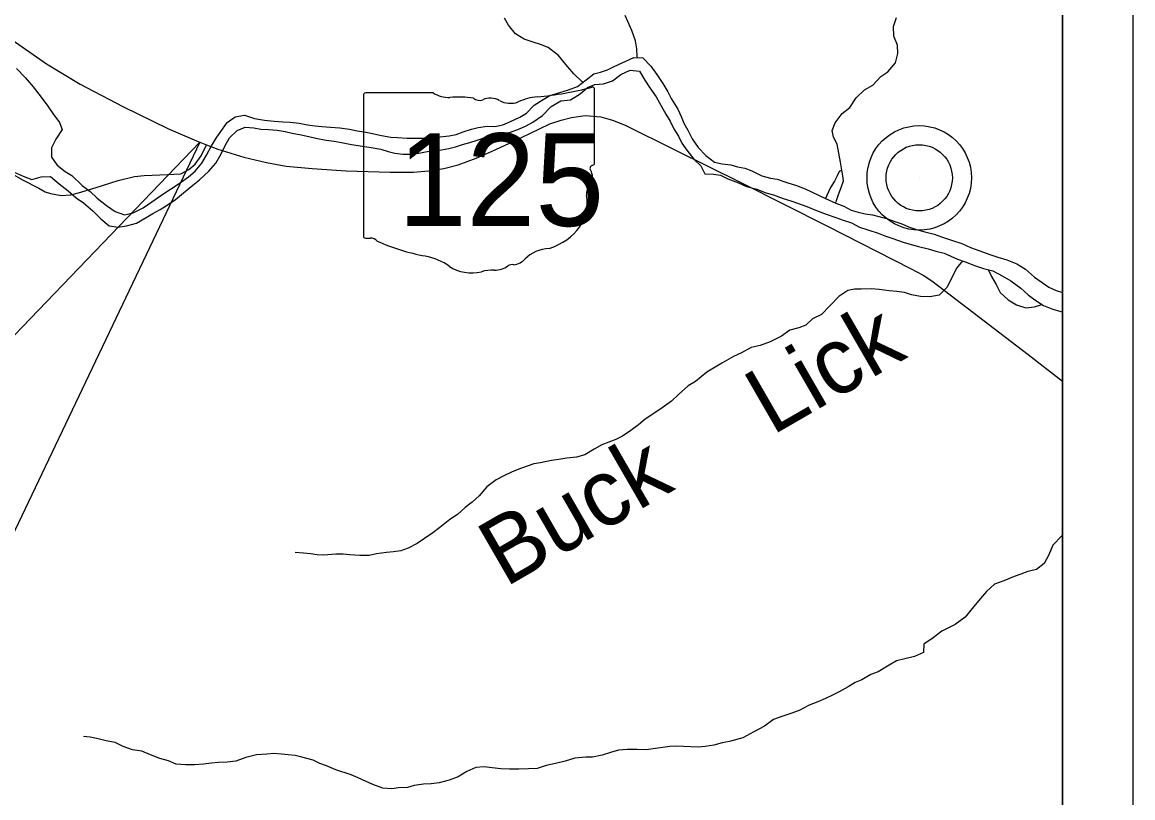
# Model space of a CAD drawing. Extents: x 0 to 34, y 0 to 22.
# Drawn here: x 7.417 to 9, y 15.178 to 16.283 of the extents above; entities that cross this region are included whole.
import ezdxf

# ---------------------------------------------------------------- set-up
doc = ezdxf.new("R2010")
doc.units = 0
for name, color, linetype in [('Default', 7, 'Continuous'), ('GM_X_Major_River', 7, 'Continuous'), ('GM_X_Minor_Lake', 7, 'Continuous'), ('GM_X_Minor_River', 7, 'Continuous'), ('GM_X_Minor_River_Text', 7, 'Continuous'), ('GM_X_State_Location', 7, 'Continuous'), ('GM_X_State_Route', 7, 'Continuous'), ('GM_X_State_Shield', 7, 'Continuous'), ('GM_X_Township_Road', 7, 'Continuous'), ('GM_X_Unincorporated', 7, 'Continuous'), ('GM_X_Unincorporated_Location', 7, 'Continuous'), ('SH_Cut_Line', 7, 'Continuous'), ('SH_Data', 7, 'Continuous'), ('SH_Text', 7, 'Continuous')]:
    doc.layers.add(name, color=color, linetype=linetype)

msp = doc.modelspace()

# ---------------------------------------------------------------- linework, layer by layer
at = {"layer": 'Default'}
msp.add_lwpolyline([(8.9, 14.1), (8.9, 18.9397), (8.8678, 19.0216), (8.806, 19.0402), (8.8461, 19.2253)], dxfattribs=at)
at = {"layer": 'GM_X_Major_River'}
msp.add_line((8.5619, 16.0315), (8.5766, 16.0251), dxfattribs=at)
for points in [[(7.4671, 16.0794), (7.4782, 16.07), (7.4877, 16.0643), (7.5025, 16.0503), (7.514, 16.0415), (7.5239, 16.0321), (7.5372, 16.0218), (7.5498, 16.0131), (7.5627, 16.0086), (7.5753, 16.0113), (7.5893, 16.0185), (7.6019, 16.0269), (7.6148, 16.0361), (7.6285, 16.0452), (7.6407, 16.0532), (7.654, 16.0627), (7.6635, 16.0707), (7.6729, 16.0818), (7.6798, 16.0936), (7.687, 16.1069), (7.6946, 16.1191), (7.7025, 16.1305), (7.709, 16.14), (7.7208, 16.148), (7.7341, 16.1503), (7.7482, 16.1458), (7.7623, 16.1435), (7.776, 16.142), (7.7885, 16.1409), (7.7988, 16.1406), (7.8117, 16.1391), (7.8239, 16.1368), (7.8346, 16.135), (7.8441, 16.1342), (7.8563, 16.1335), (7.87, 16.1324), (7.8837, 16.1305), (7.8947, 16.1282), (7.9046, 16.1267), (7.9141, 16.1249), (7.9293, 16.1215), (7.9427, 16.1192), (7.9522, 16.1185), (7.9659, 16.1178), (7.9758, 16.1178), (7.9883, 16.1178), (8.0016, 16.1178), (8.0127, 16.1194), (8.0256, 16.1209), (8.0355, 16.1229), (8.0457, 16.1267), (8.0575, 16.1305), (8.067, 16.1328), (8.08, 16.1347), (8.0906, 16.1344), (8.102, 16.1367), (8.1119, 16.1409), (8.1264, 16.1477), (8.1359, 16.1531), (8.1469, 16.1645), (8.1594, 16.1725), (8.1689, 16.1786), (8.1834, 16.1828), (8.1956, 16.1866), (8.2085, 16.1912), (8.2207, 16.2008), (8.2317, 16.2091), (8.2412, 16.2118), (8.2511, 16.2149), (8.2606, 16.2195), (8.2887, 16.2324)], [(8.2887, 16.2324), (8.3016, 16.2321), (8.3131, 16.2203), (8.3218, 16.2082), (8.3302, 16.1953), (8.3371, 16.1835), (8.3421, 16.174), (8.3516, 16.1589), (8.3562, 16.1486), (8.36, 16.1391), (8.3657, 16.1289), (8.3718, 16.1167), (8.3806, 16.1042), (8.3913, 16.0929), (8.4038, 16.0834), (8.4149, 16.0811), (8.4271, 16.0796), (8.4366, 16.077), (8.4469, 16.0747), (8.4568, 16.071), (8.4712, 16.0638), (8.4834, 16.0608), (8.4929, 16.0593), (8.507, 16.0547), (8.5207, 16.0502), (8.5329, 16.0453), (8.5619, 16.0315)], [(7.9705, 16.095), (7.9823, 16.0961), (7.9918, 16.0981), (8.0032, 16.1), (8.0146, 16.1011), (8.0252, 16.1031), (8.0347, 16.1054), (8.0446, 16.1084), (8.0549, 16.1115), (8.0656, 16.1149), (8.0766, 16.1188), (8.088, 16.1211), (8.1009, 16.1238), (8.1131, 16.1261), (8.126, 16.131), (8.1355, 16.1352), (8.145, 16.1406), (8.1587, 16.1501), (8.1712, 16.1627), (8.1846, 16.171), (8.1986, 16.1722), (8.2123, 16.181), (8.2229, 16.1897), (8.2332, 16.1939), (8.2458, 16.1951), (8.2583, 16.1993), (8.2705, 16.2081), (8.2838, 16.2146), (8.2971, 16.2131), (8.3047, 16.2002), (8.3116, 16.1892), (8.3208, 16.1763), (8.3276, 16.1638), (8.3345, 16.152), (8.3406, 16.1418), (8.3459, 16.1307), (8.3524, 16.1205), (8.3574, 16.1103), (8.3646, 16.1004), (8.3745, 16.0875), (8.3841, 16.078), (8.3898, 16.0666), (8.4024, 16.0663), (8.4122, 16.0648), (8.4229, 16.0595), (8.4378, 16.0538), (8.4496, 16.0489), (8.464, 16.0448), (8.477, 16.0399), (8.488, 16.0368), (8.5017, 16.0319), (8.5124, 16.0285), (8.5223, 16.0251), (8.5352, 16.0202), (8.5493, 16.0146), (8.563, 16.0093), (8.5767, 16.0047), (8.5874, 16.001), (8.5992, 15.9968), (8.6106, 15.9907), (8.6224, 15.987), (8.6369, 15.9821), (8.6468, 15.9783), (8.6578, 15.9749), (8.6726, 15.9696), (8.6841, 15.9662), (8.6947, 15.9632), (8.7084, 15.9598), (8.7195, 15.9568), (8.7313, 15.9538), (8.7408, 15.9496), (8.7503, 15.9451), (8.7613, 15.9413), (8.7758, 15.936), (8.7872, 15.9322), (8.8006, 15.9289), (8.8139, 15.9217), (8.8264, 15.9145), (8.8405, 15.9039), (8.8508, 15.8944), (8.8604, 15.8872), (8.8725, 15.8792), (8.8847, 15.8743), (8.8973, 15.8709), (8.9, 15.8702)], [(7.4576, 16.0631), (7.4698, 16.0525), (7.4824, 16.0426), (7.4938, 16.0328), (7.5045, 16.0256), (7.5178, 16.0142), (7.5293, 16.0028), (7.5411, 15.9926), (7.554, 15.9907), (7.5658, 15.9926), (7.5802, 15.9965), (7.5939, 16.0045), (7.6034, 16.0102), (7.6137, 16.0159), (7.6236, 16.022), (7.6357, 16.0304), (7.6468, 16.0396), (7.6601, 16.0506), (7.6699, 16.0582), (7.6829, 16.0704), (7.6931, 16.0822), (7.7003, 16.0944), (7.706, 16.1062), (7.7125, 16.1183), (7.7235, 16.1286), (7.7349, 16.1332), (7.7474, 16.1325), (7.757, 16.1306), (7.768, 16.1299), (7.7806, 16.1288), (7.792, 16.1269), (7.8019, 16.1246), (7.8148, 16.1224), (7.8258, 16.1201), (7.8357, 16.1175), (7.8502, 16.1148), (7.8616, 16.1134), (7.8723, 16.1115), (7.8864, 16.1088), (7.9023, 16.1062), (7.9145, 16.1044), (7.9282, 16.1021), (7.9389, 16.0987), (7.9484, 16.0964), (7.9598, 16.095), (7.9705, 16.095)], [(8.5766, 16.0251), (8.5776, 16.0289), (8.5807, 16.0376), (8.5842, 16.0475), (8.5877, 16.057), (8.5869, 16.0642), (8.5851, 16.0722), (8.5817, 16.0703), (8.5786, 16.0642), (8.5747, 16.0566), (8.569, 16.0472), (8.5636, 16.0351), (8.5619, 16.0315)], [(8.5766, 16.0251), (8.5881, 16.0207), (8.5988, 16.015), (8.6087, 16.012), (8.6186, 16.0098), (8.6292, 16.0083), (8.6399, 16.0056), (8.6494, 16.003), (8.6593, 15.9996), (8.6707, 15.9954), (8.6802, 15.9913), (8.6916, 15.9875), (8.7038, 15.9841), (8.7168, 15.9811), (8.7274, 15.9769), (8.7415, 15.9724), (8.7564, 15.9675), (8.7689, 15.9618), (8.7822, 15.9573), (8.7963, 15.952), (8.8077, 15.9482), (8.8207, 15.9441), (8.8348, 15.9384), (8.8473, 15.9309), (8.8599, 15.9195), (8.871, 15.9119), (8.8805, 15.9055), (8.8908, 15.9006), (8.9, 15.8977)]]:
    msp.add_lwpolyline(points, dxfattribs=at)
at = {"layer": 'GM_X_Minor_Lake'}
for points in [[(7.4091, 16.2168), (7.4213, 16.2039), (7.4327, 16.1907), (7.4441, 16.1759), (7.4537, 16.1634), (7.4609, 16.1527), (7.4701, 16.1398), (7.4739, 16.13), (7.4651, 16.1163), (7.4587, 16.1041), (7.4587, 16.0908), (7.4671, 16.0794)], [(7.4055, 16.069), (7.4184, 16.0634), (7.431, 16.0588), (7.4439, 16.0627), (7.4576, 16.0631)]]:
    msp.add_lwpolyline(points, dxfattribs=at)
at = {"layer": 'GM_X_Minor_River'}
for points in [[(8.2164, 16.1974), (8.2149, 16.1984), (8.2035, 16.2095), (8.1918, 16.2225), (8.1816, 16.2354), (8.1669, 16.2469), (8.1559, 16.2512), (8.1453, 16.2546), (8.1324, 16.2585), (8.1203, 16.2662), (8.1104, 16.2788), (8.1044, 16.2887)], [(8.2941, 16.2323), (8.2934, 16.2333), (8.2931, 16.2447), (8.2913, 16.2565), (8.286, 16.2709), (8.2763, 16.2923)], [(8.5851, 16.0722), (8.5833, 16.0836), (8.5811, 16.0965), (8.5785, 16.109), (8.5736, 16.1189), (8.5714, 16.1284), (8.5756, 16.1394), (8.5856, 16.153), (8.5967, 16.1613), (8.6059, 16.1753), (8.6177, 16.1866), (8.6296, 16.193), (8.6407, 16.2055), (8.651, 16.2123), (8.6617, 16.2251), (8.6652, 16.238), (8.6645, 16.2502), (8.6596, 16.2627), (8.659, 16.2768), (8.6632, 16.2897)], [(8.7573, 15.9427), (8.7492, 15.933), (8.7419, 15.919), (8.7353, 15.9054), (8.7239, 15.894), (8.7105, 15.8914), (8.6972, 15.8923), (8.6847, 15.8943), (8.6748, 15.8977), (8.6638, 15.8993), (8.6528, 15.9001), (8.6384, 15.9021), (8.6274, 15.9029), (8.6129, 15.9026), (8.6034, 15.9027), (8.5939, 15.9005), (8.5809, 15.8922), (8.5683, 15.8786), (8.5561, 15.8665), (8.5435, 15.8605), (8.5339, 15.8514), (8.524, 15.8473), (8.5114, 15.844), (8.4992, 15.8357), (8.4832, 15.8274), (8.4687, 15.8222), (8.4562, 15.8196), (8.4424, 15.8121), (8.431, 15.8068), (8.4142, 15.7971), (8.4024, 15.7899), (8.3928, 15.7843), (8.3768, 15.7711), (8.3661, 15.7647), (8.3527, 15.7526), (8.3424, 15.7432), (8.329, 15.7334), (8.3161, 15.7243), (8.305, 15.7172), (8.2954, 15.7092), (8.2847, 15.7013), (8.2729, 15.693), (8.2634, 15.6882), (8.2531, 15.6848), (8.2432, 15.6807), (8.2325, 15.6747), (8.2191, 15.6668), (8.207, 15.6634), (8.1933, 15.6616), (8.1818, 15.6601), (8.1716, 15.6583), (8.1556, 15.655), (8.1461, 15.6539), (8.1285, 15.6475), (8.1156, 15.6423), (8.1026, 15.6363), (8.0927, 15.631), (8.0793, 15.6212), (8.0682, 15.6084), (8.0583, 15.5993), (8.0484, 15.5914), (8.0373, 15.5816), (8.0266, 15.5744), (8.0125, 15.5631), (8.0025, 15.5556), (7.9903, 15.5473), (7.98, 15.5401), (7.967, 15.5334), (7.9567, 15.53), (7.9465, 15.5286), (7.9362, 15.5275), (7.9221, 15.5257), (7.9115, 15.5234), (7.8982, 15.5231), (7.8841, 15.524), (7.8746, 15.5252), (7.8643, 15.5252), (7.8472, 15.5238), (7.8373, 15.5242), (7.8278, 15.5254), (7.818, 15.5263), (7.8062, 15.5275)], [(8.7938, 15.9306), (8.7985, 15.9206), (8.8053, 15.9091), (8.8109, 15.8977), (8.8223, 15.8874), (8.8344, 15.8801), (8.8477, 15.8759), (8.8598, 15.8773), (8.8702, 15.8807)], [(8.9, 15.552), (8.8989, 15.5513), (8.8862, 15.5377), (8.8804, 15.524), (8.8735, 15.5119), (8.8628, 15.5033), (8.8503, 15.5003), (8.8404, 15.4965), (8.8308, 15.4932), (8.816, 15.4872), (8.803, 15.4823), (8.7915, 15.4721), (8.7801, 15.4585), (8.7712, 15.4476), (8.7609, 15.4355), (8.7468, 15.4249), (8.7277, 15.4152), (8.7155, 15.4061), (8.7021, 15.3967), (8.7017, 15.3849), (8.6887, 15.3793), (8.675, 15.376), (8.6632, 15.373), (8.6502, 15.3655), (8.6369, 15.3576), (8.6266, 15.3535), (8.614, 15.3459), (8.6045, 15.3422), (8.5945, 15.3362), (8.5816, 15.329), (8.572, 15.3241), (8.5621, 15.3193), (8.5511, 15.3148), (8.5389, 15.3099), (8.5244, 15.3024), (8.5126, 15.2983), (8.5, 15.2938), (8.4878, 15.2897), (8.4752, 15.2799), (8.46, 15.272), (8.4443, 15.2633), (8.4253, 15.2581), (8.4146, 15.2563), (8.4028, 15.253), (8.3906, 15.2511), (8.3811, 15.25), (8.3598, 15.2513), (8.3496, 15.2517), (8.3401, 15.251), (8.3302, 15.2499), (8.3195, 15.2485), (8.3062, 15.2463), (8.2937, 15.2467), (8.2792, 15.2468), (8.2671, 15.2457), (8.2556, 15.2428), (8.2438, 15.239), (8.2301, 15.2361), (8.2202, 15.2358), (8.2046, 15.2347), (8.1909, 15.2302), (8.1772, 15.2269), (8.1639, 15.2243), (8.151, 15.2198), (8.1388, 15.2191), (8.1251, 15.2188), (8.1118, 15.2189), (8.0993, 15.2193), (8.0867, 15.2206), (8.0757, 15.2221), (8.0635, 15.2211), (8.0506, 15.2154), (8.0384, 15.2079), (8.0254, 15.2034), (8.0113, 15.1993), (7.9999, 15.1979), (7.9889, 15.1976), (7.9759, 15.1957), (7.9664, 15.1928)], [(7.9664, 15.1928), (7.9535, 15.1921), (7.944, 15.1906), (7.9311, 15.1918), (7.917, 15.1968), (7.9072, 15.2014), (7.8958, 15.2064), (7.8859, 15.2107), (7.8643, 15.218), (7.8507, 15.2234), (7.8412, 15.2269), (7.8317, 15.2315), (7.8154, 15.2358), (7.8059, 15.2385), (7.796, 15.2393), (7.7865, 15.2401), (7.7755, 15.2413), (7.7656, 15.2402), (7.7512, 15.2392), (7.7359, 15.2354), (7.7215, 15.2302), (7.7093, 15.2288), (7.6967, 15.2285), (7.6868, 15.2274), (7.6754, 15.2259), (7.6625, 15.2249), (7.6496, 15.2249), (7.6367, 15.2258), (7.6257, 15.2308), (7.6131, 15.2342), (7.5999, 15.2393), (7.5877, 15.2446), (7.5741, 15.2462), (7.5608, 15.2512), (7.5498, 15.2566), (7.5369, 15.2594), (7.5274, 15.2617), (7.5141, 15.2644), (7.5046, 15.2656)]]:
    msp.add_lwpolyline(points, dxfattribs=at)
at = {"layer": 'GM_X_State_Route'}
for points in [[(7.3982, 16.261), (7.4515, 16.2235), (7.4997, 16.1945), (7.5605, 16.1628), (7.6255, 16.1308), (7.6657, 16.1138), (7.6704, 16.1119)], [(7.6704, 16.1119), (7.6798, 16.1082), (7.6958, 16.1019), (7.7328, 16.0905), (7.7653, 16.0829), (7.7934, 16.0779), (7.8305, 16.0743), (7.8786, 16.0713), (7.9413, 16.0692), (7.975, 16.0693), (7.9963, 16.0712), (8.0179, 16.0745), (8.0383, 16.0795), (8.0641, 16.089), (8.0869, 16.0993), (8.1168, 16.113), (8.1544, 16.1311), (8.1689, 16.138), (8.1854, 16.1435), (8.1999, 16.1473), (8.2195, 16.1497), (8.2418, 16.1478), (8.2582, 16.1435), (8.2765, 16.136), (8.3475, 16.1012), (8.4425, 16.054), (8.5651, 15.9924), (8.6831, 15.9321), (8.701, 15.9225), (8.7134, 15.9142), (8.7399, 15.8945), (8.851, 15.8094), (8.9, 15.7717)]]:
    msp.add_lwpolyline(points, dxfattribs=at)
at = {"layer": 'GM_X_State_Shield'}
for p, q in [((7.9033, 16.1786), (7.9033, 15.9784)), ((8.0031, 16.182), (7.9065, 16.182)), ((8.2329, 16.0823), (8.2329, 16.187)), ((8.2328, 16.0823), (8.2329, 16.0823))]:
    msp.add_line(p, q, dxfattribs=at)
for centre, major_axis, start_param, end_param in [((7.9071, 16.179), (0.00382, 0), 1.712693, 3.28349), ((8.026, 16.2052), (0.037, 0), 4.042523, 4.731795), ((8.1155, 16.4548), (0.3495, 0), 4.814394, 5.042369), ((8.2292, 16.1874), (0.00367, 0), 6.141152, 7.989035), ((8.0383, 16.0697), (0.133, 0), 1.404758, 1.657858), ((8.0685, 16.18), (0.0107, 0), 3.836095, 5.185415), ((8.0842, 16.1569), (0.0222, 0), 0.950623, 2.079405), ((8.1129, 16.1886), (0.0267, 0), 4.081561, 5.145723), ((8.1601, 16.1209), (0.0703, 0), 1.699011, 2.107814), ((8.232, 16.0746), (0.00568, 0), 1.883978, 3.671073), ((8.1959, 16.0614), (0.0341, 0), 5.934695, 6.695948), ((8.229, 16.0819), (0.00393, 0), 5.05454, 6.418171), ((8.246, 16.0385), (0.0248, 0), 2.387724, 3.262537), ((8.135, 16.0252), (0.0874, 0), 5.101752, 6.440018), ((7.9071, 15.978), (0.00385, 0), 3.00124, 4.508301), ((7.9077, 15.9985), (0.0294, 0), 4.665946, 4.897461), ((7.9137, 15.9669), (0.0106, 0), 0.519207, 1.627899), ((8.0475, 16.1467), (0.2524, 0), 4.195997, 4.488961), ((8.1719, 15.9223), (0.0479, 0), 1.647645, 2.488434), ((7.9723, 15.8885), (0.079, 0), 0.823519, 1.323587), ((8.1112, 15.9591), (0.0282, 0), 4.937069, 5.64225), ((8.0577, 15.9659), (0.0501, 0), 4.026481, 4.996735), ((8.0866, 15.8967), (0.0412, 0), 1.495662, 1.94098), ((8.0903, 15.9509), (0.0267, 0), 4.691044, 5.507374), ((8.1145, 15.9315), (0.00752, 0), 1.147584, 2.315152)]:
    msp.add_ellipse(centre, major_axis=major_axis, ratio=0.8, start_param=start_param, end_param=end_param, dxfattribs=at)
at = {"layer": 'GM_X_Township_Road'}
msp.add_lwpolyline([(7.3592, 16.0914), (7.4175, 16.0584), (7.4406, 16.0464), (7.4499, 16.0414), (7.4575, 16.0387), (7.4727, 16.0362), (7.4863, 16.0367), (7.4972, 16.0398), (7.5224, 16.0473), (7.554, 16.0573), (7.5773, 16.0629), (7.5907, 16.0644), (7.6246, 16.066), (7.6434, 16.067), (7.6548, 16.073), (7.6636, 16.0806), (7.6723, 16.0925), (7.6798, 16.1082)], dxfattribs=at)
at = {"layer": 'GM_X_Unincorporated'}
for radius in [0.0744, 0.0472]:
    msp.add_circle((8.6956, 16.0611), radius, dxfattribs=at)
at = {"layer": 'GM_X_Unincorporated_Location'}
msp.add_line((8.6956, 16.0611), (8.6956, 16.0611), dxfattribs=at)
at = {"layer": 'SH_Cut_Line'}
msp.add_lwpolyline([(2.4352, 14.1), (8.9, 14.1), (8.9, 20.9), (2.4845, 20.9), (2.4809, 20.6393), (2.4757, 20.2566), (2.4573, 18.9074), (2.4581, 18.1825), (2.4581, 18.1772), (2.4586, 17.7785), (2.4545, 17.2795), (2.4313, 15.0183), (2.4372, 14.2719)], close=True, dxfattribs=at)
at = {"layer": 'SH_Data'}
for p, q in [((9, 21), (9, 14)), ((8.9, 20.9), (8.9, 14.1))]:
    msp.add_line(p, q, dxfattribs=at)
at = {"layer": 'SH_Text'}
msp.add_lwpolyline([(7.2097, 15.6335), (7.6704, 16.1119), (7.2097, 15.147)], close=True, dxfattribs=at)

# ---------------------------------------------------------------- texts
at = {"layer": 'GM_X_Minor_River_Text'}
for s, rotation, p in [('Lick', 30.0024, (8.4856, 15.6934)), ('Buck', 30.0026, (8.1055, 15.4772))]:
    msp.add_text(s, height=0.0947, rotation=rotation, dxfattribs=at).set_placement(p)
at = {"layer": 'GM_X_State_Location'}
msp.add_text('125', height=0.000189, rotation=0, dxfattribs=at).set_placement((7.9975, 16.0514))
for s in ['s', 'r']:
    msp.add_text(s, height=0.000189, dxfattribs=at).set_placement((8.0644, 16.0652))
at = {"layer": 'GM_X_State_Shield'}
msp.add_text('125', height=0.13184, dxfattribs=at).set_placement((7.9524, 15.9926))

doc.saveas('drawing.dxf')
